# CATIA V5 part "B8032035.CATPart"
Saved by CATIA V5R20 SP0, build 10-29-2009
Part number: B8032035
Revision: 5
Definition: design
Nomenclature: B8032035
Source: made
Description: NOT SPECIFIED
Bounding box of the stored display mesh (mm): x -16 to 16, y -16 to 16, z 0 to 35
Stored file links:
  C:\Users\Utente\Desktop\3D files B803\B8032035.CATPart
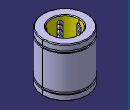
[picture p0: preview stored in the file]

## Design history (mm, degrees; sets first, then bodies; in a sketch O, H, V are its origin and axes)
Body1 "MANIFOLD_SOLID_BREP #38" (main body)
  Solid1: solid without history
Body2 "MANIFOLD_SOLID_BREP #76"
  Solid2: solid without history
Body3 "MANIFOLD_SOLID_BREP #114"
  Solid3: solid without history
Body4 "MANIFOLD_SOLID_BREP #152"
  Solid4: solid without history
Body5 "MANIFOLD_SOLID_BREP #190"
  Solid5: solid without history
Body6 "MANIFOLD_SOLID_BREP #228"
  Solid6: solid without history
Body7 "MANIFOLD_SOLID_BREP #266"
  Solid7: solid without history
Body8 "MANIFOLD_SOLID_BREP #304"
  Solid8: solid without history
Body9 "MANIFOLD_SOLID_BREP #2066"
  Solid9: solid without history
Body10 "MANIFOLD_SOLID_BREP #2104"
  Solid10: solid without history
Body11 "MANIFOLD_SOLID_BREP #2142"
  Solid11: solid without history
Body12 "MANIFOLD_SOLID_BREP #2180"
  Solid12: solid without history
Body13 "MANIFOLD_SOLID_BREP #2218"
  Solid13: solid without history
Body14 "MANIFOLD_SOLID_BREP #2256"
  Solid14: solid without history
Body15 "MANIFOLD_SOLID_BREP #2294"
  Solid15: solid without history
Body16 "MANIFOLD_SOLID_BREP #2332"
  Solid16: solid without history
Body17 "MANIFOLD_SOLID_BREP #2370"
  Solid17: solid without history
Body18 "MANIFOLD_SOLID_BREP #2408"
  Solid18: solid without history
Body19 "MANIFOLD_SOLID_BREP #2446"
  Solid19: solid without history
Body20 "MANIFOLD_SOLID_BREP #2484"
  Solid20: solid without history
Body21 "MANIFOLD_SOLID_BREP #2522"
  Solid21: solid without history
Body22 "MANIFOLD_SOLID_BREP #2560"
  Solid22: solid without history
Body23 "MANIFOLD_SOLID_BREP #2598"
  Solid23: solid without history
Body24 "MANIFOLD_SOLID_BREP #2636"
  Solid24: solid without history
Body25 "MANIFOLD_SOLID_BREP #2674"
  Solid25: solid without history
Body26 "MANIFOLD_SOLID_BREP #2712"
  Solid26: solid without history
Body27 "MANIFOLD_SOLID_BREP #2750"
  Solid27: solid without history
Body28 "MANIFOLD_SOLID_BREP #2788"
  Solid28: solid without history
Body29 "MANIFOLD_SOLID_BREP #2826"
  Solid29: solid without history
Body30 "MANIFOLD_SOLID_BREP #2864"
  Solid30: solid without history
Body31 "MANIFOLD_SOLID_BREP #2902"
  Solid31: solid without history
Body32 "MANIFOLD_SOLID_BREP #2940"
  Solid32: solid without history
Body33 "MANIFOLD_SOLID_BREP #2978"
  Solid33: solid without history
Body34 "MANIFOLD_SOLID_BREP #3016"
  Solid34: solid without history
Body35 "MANIFOLD_SOLID_BREP #3054"
  Solid35: solid without history
Body36 "MANIFOLD_SOLID_BREP #3092"
  Solid36: solid without history
Body37 "MANIFOLD_SOLID_BREP #3130"
  Solid37: solid without history
Body38 "MANIFOLD_SOLID_BREP #3168"
  Solid38: solid without history
Body39 "MANIFOLD_SOLID_BREP #3206"
  Solid39: solid without history
Body40 "MANIFOLD_SOLID_BREP #3244"
  Solid40: solid without history
Body41 "MANIFOLD_SOLID_BREP #3282"
  Solid41: solid without history
Body42 "MANIFOLD_SOLID_BREP #3320"
  Solid42: solid without history
Body43 "MANIFOLD_SOLID_BREP #3358"
  Solid43: solid without history
Body44 "MANIFOLD_SOLID_BREP #3396"
  Solid44: solid without history
Body45 "MANIFOLD_SOLID_BREP #3434"
  Solid45: solid without history
Body46 "MANIFOLD_SOLID_BREP #3472"
  Solid46: solid without history
Body47 "MANIFOLD_SOLID_BREP #3510"
  Solid47: solid without history
Body48 "MANIFOLD_SOLID_BREP #3548"
  Solid48: solid without history
Body49 "MANIFOLD_SOLID_BREP #3586"
  Solid49: solid without history
Body50 "MANIFOLD_SOLID_BREP #3624"
  Solid50: solid without history
Body51 "MANIFOLD_SOLID_BREP #3662"
  Solid51: solid without history
Body52 "MANIFOLD_SOLID_BREP #3700"
  Solid52: solid without history
Body53 "MANIFOLD_SOLID_BREP #3738"
  Solid53: solid without history
Body54 "MANIFOLD_SOLID_BREP #3776"
  Solid54: solid without history
Body55 "MANIFOLD_SOLID_BREP #3814"
  Solid55: solid without history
